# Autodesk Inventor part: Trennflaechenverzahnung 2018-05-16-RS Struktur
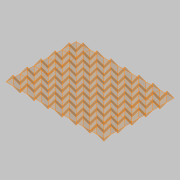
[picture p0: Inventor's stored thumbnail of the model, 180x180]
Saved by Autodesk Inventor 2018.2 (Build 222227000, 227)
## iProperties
Created: 2018-05
Part Number: Trennflaechenverzahnung 2018-05-16-RS Struktur
Material: ---
Document SubType Name: Modeling
Designer: Roland
Appearance: grau
Author: Roland
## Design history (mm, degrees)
node "Blöcke"
  sketch "Rechteck abgerundet"
    geometry: L1 (182.926, 40.686)-(222.735, 40.686); L2 (229.51, 47.461)-(229.51, 80.56); L3 (176.151, 47.461)-(176.151, 80.56); L4 (182.926, 87.335)-(222.735, 87.335); A1 r 6.775 centre (222.735, 47.461) between (222.735, 40.686) and (229.51, 47.461); A2 r 6.775 centre (222.735, 80.56) between (229.51, 80.56) and (222.735, 87.335); A3 r 6.775 centre (182.926, 47.461) between (176.151, 47.461) and (182.926, 40.686); A4 r 6.775 centre (182.926, 80.56) between (182.926, 87.335) and (176.151, 80.56); 1 further point
    constraints: 8 end point, 8 point on circle, 8 tangent, 4 centre point, 3 equal radius, 3 perpendicular, 1 coincident
sketch "Skizze1"
  geometry: L1 (0, 0)-(-2, 0); L2 (-2, 0)-(-2, -2); L3 (-2, -2)-(0, -2); L4 (0, -2)-(0, 0); L5 (0, 0)-(-2, -2); L6 (-2, 0)-(0, -2); 1 further point
  constraints: 12 end point, 2 parallel, 2 perpendicular, 1 coincident, 1 horizontal
  dimensions: "d" = 2 distance of L1.start L1.end
feature "Extrusionsfläche1" dims "d9" = 10, "d10" = -15 deg
pattern_circular "Runde Anordnung1" dims angle "d7" = 360 deg
feature "Fläche heften1"
pattern_circular "Runde Anordnung3" dims angle "d15" = 360 deg
feature "Fläche heften3"
feature "Fläche heften28"
pattern_linear "Rechteckige Anordnung1" dims "d19" = 4 (= 2 x d), "d22" = 4 (= 2 x d)
node "Fläche3"
node "Fläche4"
node "Fläche7"
node "Fläche8"
node "Fläche9"
node "Fläche10"
node "Fläche11"
node "Fläche12"
node "Fläche13"
node "Fläche14"
node "Fläche15"
node "Fläche16"
node "Fläche17"
node "Fläche18"
node "Fläche19"
node "Fläche20"
node "Fläche21"
node "Fläche22"
node "Fläche23"
node "Fläche24"
node "Fläche25"
node "Fläche26"
node "Fläche27"
node "Fläche28"
node "Fläche29"
node "Fläche30"
node "Fläche31"
node "Fläche32"
node "Fläche33"
node "Fläche34"
node "Fläche35"
node "Fläche36"
node "Fläche37"
node "Fläche38"
node "Fläche39"
node "Fläche40"
node "Fläche41"
node "Fläche42"
node "Fläche43"
node "Fläche44"
feature "Extrusionsfläche2"
feature "Fläche heften2"
feature "Fläche heften4"
feature "Fläche heften5"
feature "Fläche heften6"
feature "Fläche heften7"
feature "Fläche heften8"
feature "Fläche heften9"
feature "Fläche heften10"
feature "Fläche heften11"
feature "Fläche heften12"
feature "Fläche heften13"
feature "Fläche heften14"
feature "Fläche heften15"
feature "Fläche heften16"
feature "Fläche heften17"
feature "Fläche heften18"
feature "Fläche heften19"
feature "Fläche heften20"
feature "Fläche heften21"
feature "Fläche heften22"
feature "Fläche heften23"
feature "Fläche heften24"
feature "Fläche heften25"
feature "Fläche heften26"
feature "Fläche heften27"
feature "Fläche heften29"
feature "Fläche heften30"
feature "Fläche heften31"
feature "Fläche heften32"
feature "Fläche heften33"
feature "Fläche heften34"
feature "Fläche heften35"
feature "Fläche heften36"
feature "Fläche heften37"
feature "Fläche heften38"
